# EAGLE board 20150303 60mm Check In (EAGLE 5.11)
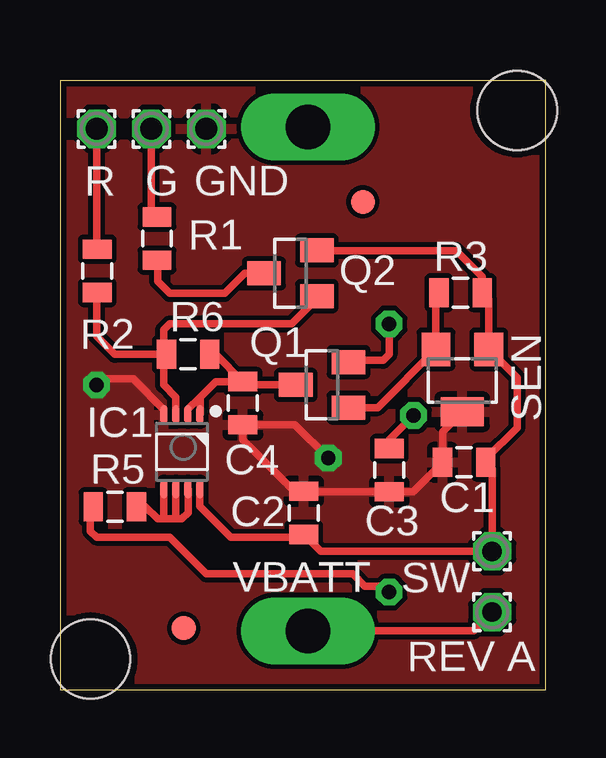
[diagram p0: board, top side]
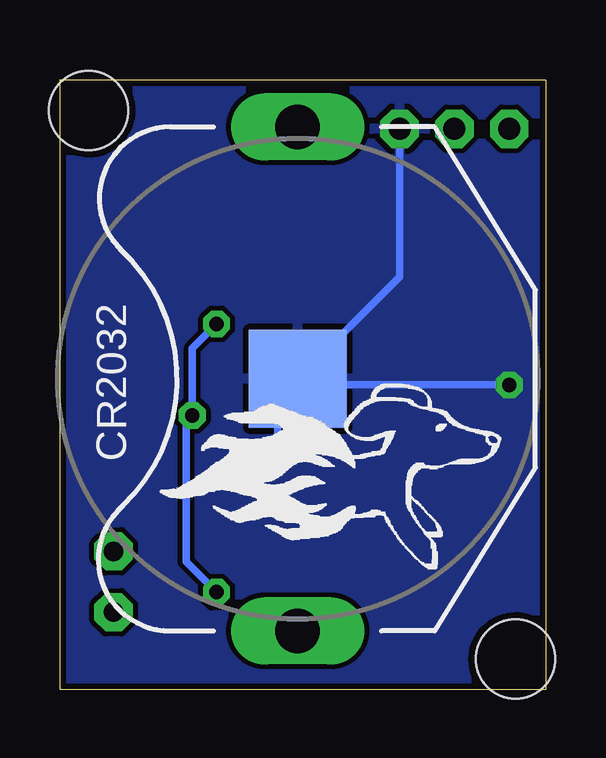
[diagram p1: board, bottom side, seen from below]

Size 20.24 x 25.41 mm. Coordinates in mm from the lower left corner, seen from the top.
Outline: 20.24,25.4 20.24,0 0,0 0,25.4 20.24,25.4
Outline: 20.24,25.4 20.24,25.41
Copper layers (1*16): Top 0.035mm / dielectric 1.5mm / Bottom 0.035mm
Design rules "SparkFun": minimum track width 8mil, minimum drill 20mil, track to track 8mil, track to pad 8mil, pad to pad 8mil, via to via 8mil, smd to smd 8mil, copper to edge 10mil, drill to drill 8mil, minimum pad ring 12mil, minimum via ring 10mil, stop-mask expansion 4mil, vias tented up to drill 25mil, thermal gap 10mil

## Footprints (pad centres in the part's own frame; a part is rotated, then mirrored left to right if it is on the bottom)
0805 = smd 0.8 x 1.2: 1 -0.9,0; 2 0.9,0
BATTERY_20MM_PTH_COMPACT = drill 1.854 long: 1 -10.5,0; 3 10.5,0 | smd 4.064 x 4.064: 2 0,0
1,6/0,9 = drill 0.914 pad 1.6 octagon: 1 0,0
TSSOP50P310X90-8N_MAB08A_US8 = smd 0.8 x 0.3: 1 -1.55,0.75; 2 -1.55,0.25; 3 -1.55,-0.25; 4 -1.55,-0.75; 5 1.55,-0.75; 6 1.55,-0.25; 7 1.55,0.25; 8 1.55,0.75
FIDUCIAL-1X2 = smd 1 x 1: 1 0,0
STAND-OFF = hole 3.302: 0,0
SOT23 = smd 1 x 1.4: 1 -0.95,-1.1; 2 0.95,-1.1; 3 0,1.1
SOT23-W = smd 1.2 x 1.4: 1 -1.1,-1.3; 2 1.1,-1.3 | smd 1.8 x 1.2: 3 0,1.3
1,6/0,8SWITCH = drill 0.813 pad 1.6 octagon: 1 0,0; 2 2.54,0

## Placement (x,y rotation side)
C1  0.1uf  [0805]  16.84,9.47 180 top
C2  0.1uf  [0805]  10.16,7.37 90 top
C3  0.1uf  [0805]  13.72,9.14 270 top
C4  0.1uf  [0805]  7.62,11.94 270 top
CR2032  [BATTERY_20MM_PTH_COMPACT]  10.34,12.95 90 bottom
G  WIREPAD1,6/0,9  [1,6/0,9]  3.81,23.37 0 top
GND  WIREPAD1,6/0,9  [1,6/0,9]  6.1,23.37 0 top
IC1  NC7WP00K8X  [TSSOP50P310X90-8N_MAB08A_US8]  5.08,9.91 270 top
JP2  FIDUCIAL1X2  [FIDUCIAL-1X2]  5.16,2.57 90 top
JP3  FIDUCIAL1X2  [FIDUCIAL-1X2]  12.62,20.32 90 top
JP6  STAND-OFF  [STAND-OFF]  1.27,1.27 0 top
JP7  STAND-OFF  [STAND-OFF]  19.05,24.13 0 top
Q1  FDN338P  [SOT23]  10.92,12.7 90 top
Q2  FDN338P  [SOT23]  9.6,17.35 90 top
R  WIREPAD1,6/0,9  [1,6/0,9]  1.52,23.37 0 top
R1  3.3K  [0805]  4.04,18.8 270 top
R2  10k  [0805]  1.55,17.45 90 top
R3  50K  [0805]  16.69,16.54 0 top
R5  100k  [0805]  2.29,7.62 0 top
R6  100K  [0805]  5.33,13.97 180 top
SEN  A1203LH  [SOT23-W]  16.76,12.88 180 top
SW  SWITCHLEADSB  [1,6/0,8SWITCH]  18.01,3.23 90 top
U$2  BYRNEDAWGBIG_LABEL  [BYRNEDAWGBIGLABEL]  4.06,8.38 0 bottom

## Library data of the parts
C1-C4 CR2032 JP2 JP3 JP6 JP7 R1-R3 R5 R6 = SparkFun
G GND R = wirepad
IC1 = fairchild-tinylogic
Q1 Q2 = fairchild-semic
SEN = allegro; MF: ALLEGRO MICROSYSTEMS, INC.; MPN: A1203LLHLT-T; OC_FARNELL: 1791384; OC_NEWARK: 31K6608
SW = User_Created
U$2 = logo

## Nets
GND: C1.2 C2.2 C3.2 C4.2 CR2032.2 GND.1 IC1.4 SEN.3
GREEN_LED: G.1 R1.1
N$1: IC1.3 Q2.1 R2.1 R6.2
N$2: C4.1 IC1.1 IC1.2 Q1.3 R6.1
N$3: Q2.3 R1.2
N$4: C3.1 Q1.2 R5.1
N$5: IC1.5 IC1.6 IC1.7 R5.2
RED_LED: R2.2 R.1
SENSOR_OUT: Q1.1 R3.1 SEN.2
VBATT: CR2032.1 SW.1
VCC: C1.1 C2.1 IC1.8 Q2.2 R3.2 SEN.1 SW.2

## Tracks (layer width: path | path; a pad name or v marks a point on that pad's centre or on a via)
GND  (via drill 0.6)
  Top 0.305: SEN.3 15.94,10.75 C1.2 14.71,8.24 C3.2 10.18,8.24 C2.2 9.77,8.27 7.62,10.41 C4.2 9.79,11.04 v11.18,9.65 | IC1.4 4.33,11.67 3.05,12.95 1.78,12.95 v1.52,12.7
  Bottom 0.305: GND.1 6.1,17.2 CR2032.2 | v11.18,9.65 11.18,12.12 CR2032.2 | v1.52,12.7 10.08,12.7 CR2032.2
  pour Bottom: 0,0 0,25.4 20.32,25.4 20.32,0
  pour Top: 0,0 0,25.4 20.32,25.4 20.32,0
GREEN_LED
  Top 0.305: R1.1 3.81,19.7 G.1
N$1
  Top 0.305: IC1.3 4.83,12.19 4.32,12.7 4.32,13.85 R6.2 | Q2.1 10.7,16.29 9.65,15.24 4.57,15.24 4.32,14.99 4.32,14.09 R6.2 | R6.2 2.29,13.97 1.52,14.73 1.52,16.52 R2.1
N$2
  Top 0.305: R6.1 6.49,13.97 C4.1 | C4.1 6.49,12.84 5.84,12.19 | 5.84,12.19 5.84,11.47 IC1.1 | IC1.2 5.33,11.68 5.84,12.19 | Q1.3 7.76,12.7 C4.1
N$3
  Top 0.305: Q2.3 7.7,17.35 6.86,16.51 4.57,16.51 4.06,17.02 4.06,17.87 R1.2
N$4  (via drill 0.6)
  Top 0.305: C3.1 13.72,10.41 v14.73,11.43 | v13.72,15.24 13.72,13.97 13.46,13.72 12.09,13.72 Q1.2 | v13.72,4.06 13.46,4.32 12.7,4.32 12.19,4.83 6.1,4.83 4.57,6.35 1.52,6.35 1.27,6.6 1.27,7.5 R5.1
  Bottom 0.305: v13.72,15.24 14.73,14.22 v14.73,11.43 14.99,11.18 14.99,5.33 v13.72,4.06
N$5
  Top 0.305: R5.2 3.56,7.62 4.06,7.11 4.32,7.11 | 4.83,7.11 4.32,7.11 | 4.83,7.11 5.08,7.11 5.33,7.37 IC1.7 | IC1.5 4.33,7.12 4.32,7.11 | IC1.6 4.83,7.12 4.83,7.11
RED_LED
  Top 0.305: R2.2 1.52,18.35 R.1
SENSOR_OUT
  Top 0.305: R3.1 15.66,16.41 SEN.2 13.24,11.75 Q1.1
VBATT
  Top 0.305: CR2032.1 17.24,2.45 SW.1
VCC
  Top 0.305: Q2.2 10.71,18.29 16.51,18.29 17.59,17.21 R3.2 17.86,16.26 SEN.1 19.05,12.99 19.05,10.92 17.74,9.61 C1.1 18.01,9.21 SW.2 10.86,5.77 C2.1 10.04,6.35 7.11,6.35 5.83,7.63 IC1.8

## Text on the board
tNames: VBATT | REV A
